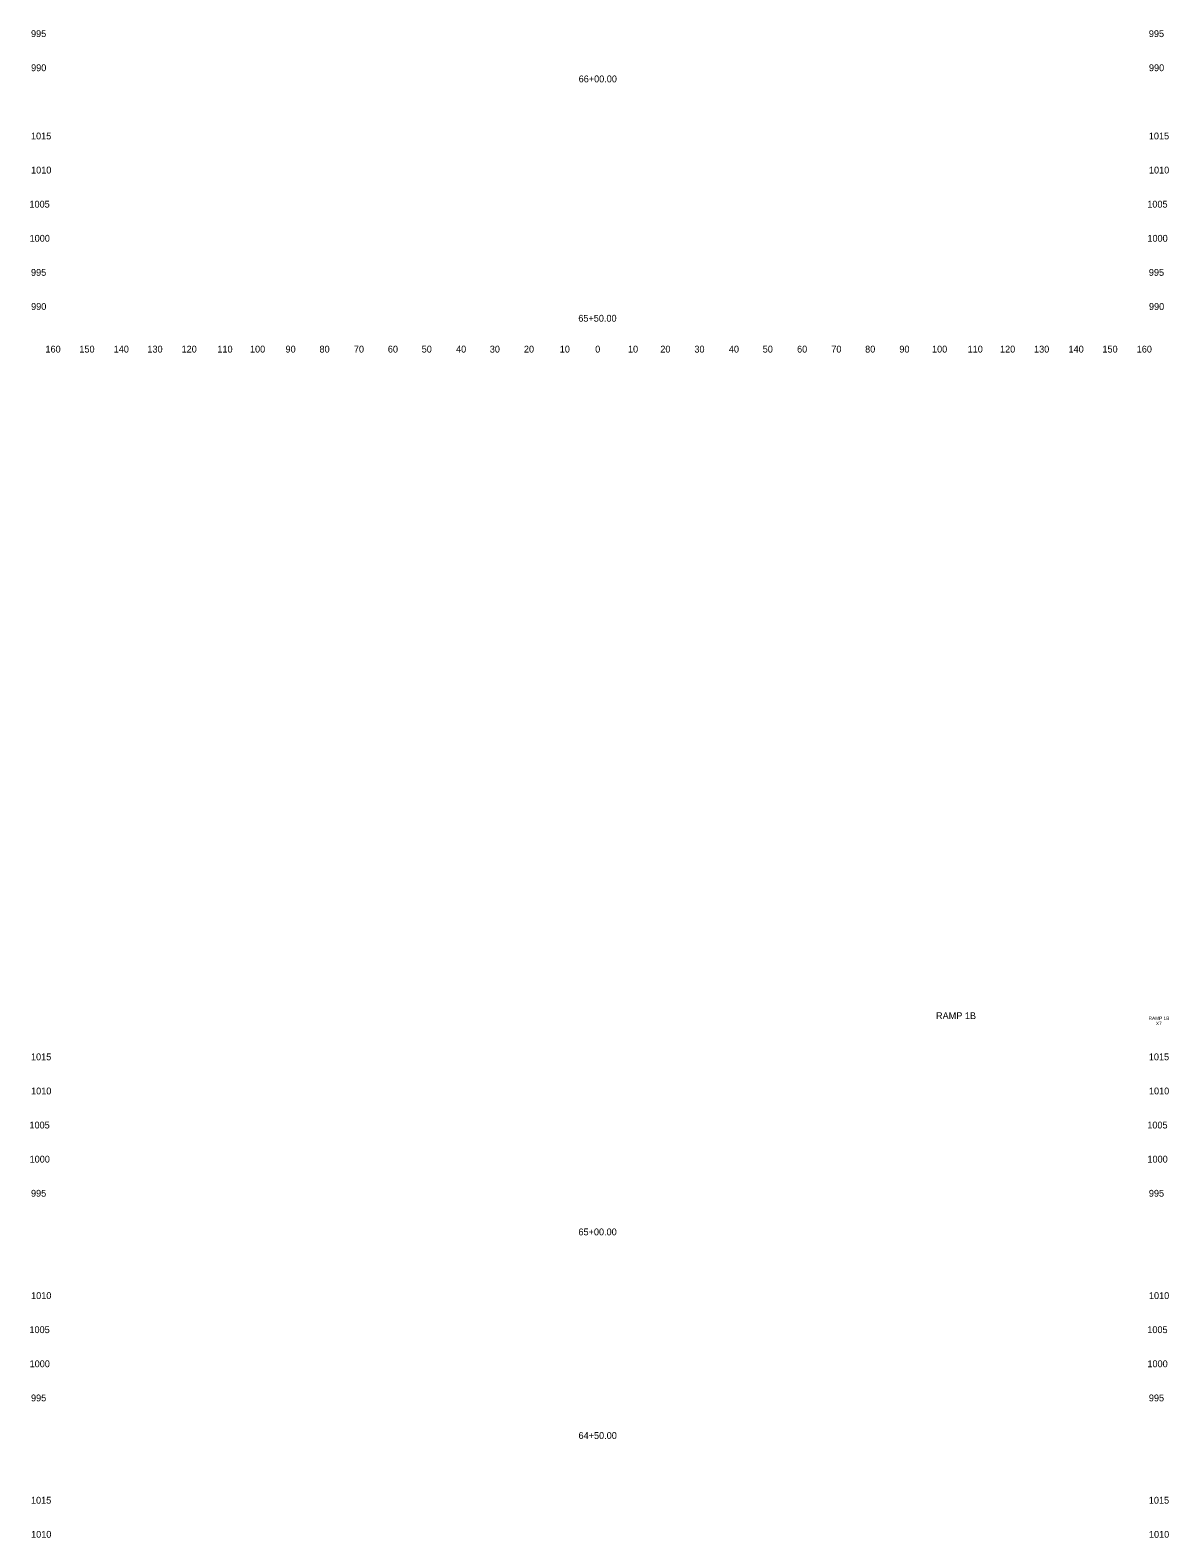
# Model space of a CAD drawing. Extents: x 4994 to 5843, y 4997 to 8804.
# Drawn here: x 4993.6 to 5327.5, y 7450 to 7892 of the extents above; entities that cross this region are included whole.
import ezdxf

# ---------------------------------------------------------------- set-up
doc = ezdxf.new("R2010")
doc.units = 0
for name, color, linetype in [('CLS_Search_Dist', 7, 'Continuous'), ('RD_XE_Ground', 7, 'Continuous'), ('UC_PD_Text', 7, 'Continuous')]:
    doc.layers.add(name, color=color, linetype=linetype)

msp = doc.modelspace()

# ---------------------------------------------------------------- texts
at = {"layer": 'CLS_Search_Dist'}
for s, p in [('995', (4993.86, 7890)), ('995', (5321.66, 7890)), ('990', (4993.89, 7880)), ('990', (5321.69, 7880)), ('1015', (4993.85, 7860)), ('1015', (5321.65, 7860)), ('1010', (4993.88, 7850)), ('1010', (5321.68, 7850)), ('1005', (4993.4, 7840)), ('1005', (5321.2, 7840)), ('1000', (4993.44, 7830)), ('1000', (5321.24, 7830)), ('995', (4993.86, 7820)), ('995', (5321.66, 7820)), ('990', (4993.89, 7810)), ('990', (5321.69, 7810)), ('160', (4998.1, 7797.5)), ('150', (5008.04, 7797.5)), ('140', (5018.1, 7797.5)), ('130', (5027.99, 7797.5)), ('120', (5038.01, 7797.5)), ('110', (5048.51, 7797.5)), ('100', (5058.07, 7797.5)), ('90', (5068.5, 7797.5)), ('80', (5078.46, 7797.5)), ('70', (5088.54, 7797.5)), ('60', (5098.5, 7797.5)), ('50', (5108.43, 7797.5)), ('40', (5118.5, 7797.5)), ('30', (5128.39, 7797.5)), ('20', (5138.4, 7797.5)), ('10', (5148.91, 7797.5)), ('0', (5159.3, 7797.5)), ('0', (5159.3, 7797.5)), ('10', (5168.91, 7797.5)), ('20', (5178.4, 7797.5)), ('30', (5188.39, 7797.5)), ('40', (5198.5, 7797.5)), ('50', (5208.43, 7797.5)), ('60', (5218.5, 7797.5)), ('70', (5228.54, 7797.5)), ('80', (5238.46, 7797.5)), ('90', (5248.5, 7797.5)), ('100', (5258.07, 7797.5)), ('110', (5268.51, 7797.5)), ('120', (5278.01, 7797.5)), ('130', (5287.99, 7797.5)), ('140', (5298.1, 7797.5)), ('150', (5308.04, 7797.5)), ('160', (5318.1, 7797.5)), ('1015', (4993.85, 7590)), ('1015', (5321.65, 7590)), ('1010', (4993.88, 7580)), ('1010', (5321.68, 7580)), ('1005', (4993.4, 7570)), ('1005', (5321.2, 7570)), ('1000', (4993.44, 7560)), ('1000', (5321.24, 7560)), ('995', (4993.86, 7550)), ('995', (5321.66, 7550)), ('1010', (4993.88, 7520)), ('1010', (5321.68, 7520)), ('1005', (4993.4, 7510)), ('1005', (5321.2, 7510)), ('1000', (4993.44, 7500)), ('1000', (5321.24, 7500)), ('995', (4993.86, 7490)), ('995', (5321.66, 7490)), ('1015', (4993.85, 7460)), ('1015', (5321.65, 7460)), ('1010', (4993.88, 7450)), ('1010', (5321.68, 7450))]:
    msp.add_text(s, height=2, dxfattribs=at).set_placement(p)
at = {"layer": 'RD_XE_Ground'}
for s, p in [('66+00.00', (5154.45, 7876.74)), ('65+50.00', (5154.35, 7806.56)), ('65+00.00', (5154.39, 7538.68)), ('64+50.00', (5154.42, 7478.97))]:
    msp.add_text(s, height=2, dxfattribs=at).set_placement(p)
at = {"layer": 'UC_PD_Text'}
for s, height, p in [('RAMP 1B', 2, (5259.24, 7602.06)), ('RAMP 1B', 1, (5321.59, 7601.8)), ('X7', 1, (5323.74, 7600.3))]:
    msp.add_text(s, height=height, dxfattribs=at).set_placement(p)

doc.saveas('drawing.dxf')
